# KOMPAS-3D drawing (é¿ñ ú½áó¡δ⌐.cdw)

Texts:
  ПЛК.303120.00.00 СБ
  Редуктор цилиндрический  двухступенчатый Сборочный чертеж
  Ревин ЕЕ
  Noncommercial version
  Лит-Масса-Масштаб
  Материал-Предприятие
  Технические требования на редуктор.
  Все детали и их элементы, расположенные снаружи редуктора, должны иметь антикаррозийное покрытие.
  При окончательной сборке редуктора плоские поверхности разъема крышки корпуса и основания корпуса очистить от смазки и покрыть тонким слоем герметика.
  Производственные испытания редуктора на стенде производить после окончательной сборки и регулировки подшипников только через два часа выдержки.
  Эксплуатационную регулировку подшипников проводить в соответсвии с плановым ремонтом.
  После сборки редуктор испытывать на стенде, под нагрузкой, не менее двух часов.
  После испытания на стенде имеющуюся смазку слить, внутреннюю полость редуктора промыть керосином и залить свежую смазку.
  Уровень масла проверять каждую смену.
  Наружные необработанные поверхности редуктора грунтовать и красить светло-серой нитроэмалью, внутренние необработанные поверхности красить только
  красной маслостойкой краской.
  Технические требования
  Частота вращения ведущего вала редуктора n1=949 об/мин
  Крутящий момент на ведомом валу редуктора Т3=1429 Н*м
  Передаточное отношение быстроходной ступени i12=4,66
  Передаточное отношение тихоходной ступени i34=4.0
  Число зубев шестерни быстроходной ступени  z1=22
  Число зубьев колеса быстроходной ступени z2=101
  Число зубьев шестерни тихоходной ступени z3=22
  Число зубьев колеса тихоходной ступени z4=89
  Модуль зацепления быстроходной ступени mn12=2,0 мм
  Модуль зацепления тихоходной ступени mn34=2.5 мм
  Угол наклона зубьев быстроходной ступени  12 =29 16
  Symbol
  Угол наклона зубьев тихоходной ступени  34=29 53
  ACAD_ISO10W100_RGB_255_128_0_SC_1_THICK_0.15
  ACAD_ISO10W100_RGB_51_51_51_SC_1_THICK_0.15
  ACAD_ISO10W100_RGB_255_128_0_SC_0.5_THICK_0.15
  ACAD_ISO10W100_RGB_255_64_0_SC_1_THICK_0.15
  ACAD_ISO08W100_RGB_255_64_0_SC_1_THICK_0.15
  ACAD_ISO03W100_RGB_0_0_0_SC_0.3_THICK_0.15
  ACAD_ISO10W100_RGB_255_63_0_SC_1_THICK_0.15
  ACAD_ISO10W100_RGB_255_63_0_SC_0.25_THICK_0.15
  ACAD_ISO10W100_RGB_255_63_0_SC_0.5_THICK_0.15
  gost6_RGB_255_128_0_SC_1_THICK_0.15
  ACAD_ISO10W100_RGB_51_51_51_SC_1_THICK_0.18
  ACAD_ISO10W100_RGB_0_0_0_SC_1_THICK_0.18
  gost6_RGB_255_128_0_SC_0.5_THICK_0.15
  ACAD_ISO10W100_RGB_51_51_51_SC_0.1_THICK_0.25
  POLYLINE_STYLE_0.18_RGB_0_0_255
  ACAD_ISO10W100_RGB_255_128_0_SC_0.75_THICK_0.15
  ACAD_ISO03W100_RGB_0_0_255_SC_0.25_THICK_0.5
  ACAD_ISO03W100_RGB_0_0_0_SC_0.1_THICK_0.15
  ACAD_ISO10W100_RGB_255_128_0_SC_1_THICK_0.18
  ACAD_ISO10W100_RGB_51_51_51_SC_1_THICK_0.25
  ACAD_ISO10W100_RGB_0_0_255_SC_0.5_THICK_0.15
  СONTINUOUS_RGB_0_0_0_THICK_0.5
  ACAD_ISO10W100_RGB_255_128_0_SC_0.25_THICK_0.15
  ACAD_ISO10W100_RGB_255_64_0_SC_1_THICK_0.18
  Стили документа
  Подшипник 36207K ГОСТ 831-75
  Подшипник
  ГОСТ
  Подшипник 7212А ГОСТ 27365-87
  Подшипник207 ГОСТ 8338-75
  Подшипник209 ГОСТ 8338-75
  Манжета
  Шайба 8 Л БрКМц3-1 ГОСТ 6402-70
  Шайба пружинная
  Шайба
  БрКМц3-1
  БрКМц3-1 ГОСТ 18175-78
  Болт М8-6g x 22.109.30ХГСА ГОСТ 7808-70
  Болт
  .30ХГСА
  Сталь 30ХГСА ГОСТ 4543-71
  ANSI37
  Редуктор цилиндрический
  двухступенчатый
  Сборочный чертеж
  Вавилин В.В
  РЦО.112.00.00 СБ-
Dimensions and other numbers on the sheet: 20; 4 отв.; 125; 160; 482; 526; 594; 106; 208; 370; 1; 2; 8; 9; 15; 22; 23; 24; 25; 32; 34; 26; 27; 33; 35; 31; 30; 37; 48; 70; 55; 029; -6g; 1:1; 3; 4; 5; 6; 7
